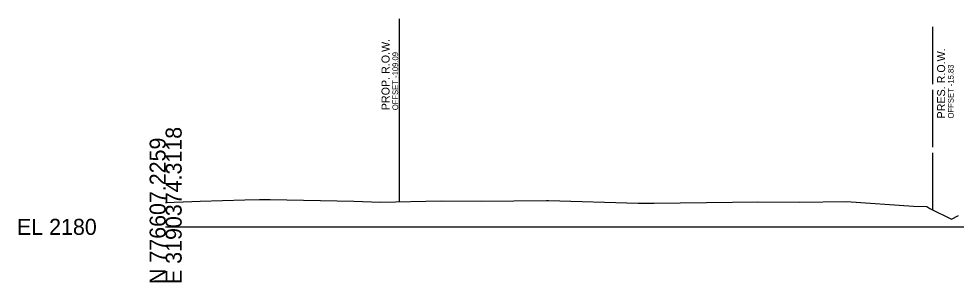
# Model space of a CAD drawing. Extents: x -26 to 303, y -10 to 13517.
# Drawn here: x -25.7 to 138.3, y 9490.3 to 9536.4 of the extents above; entities that cross this region are included whole.
import ezdxf

# ---------------------------------------------------------------- set-up
doc = ezdxf.new("R2010")
doc.units = 0
for name, color, linetype in [('DESIGN - ROW - Right-of-Way and Easement Labels', 7, 'Continuous'), ('DESIGN - ROW - Right-of-Way Linework', 7, 'Continuous'), ('DESIGN - SHEET - Light Grid', 7, 'Continuous'), ('SURVEY - GROUND - Top of Ground', 7, 'Continuous'), ('SURVEY - PROPERTY - ROW Lines', 7, 'Continuous'), ('SURVEY - PROPERTY - ROW Lines Text', 7, 'Continuous')]:
    doc.layers.add(name, color=color, linetype=linetype)

msp = doc.modelspace()

# ---------------------------------------------------------------- linework, layer by layer
at = {"layer": 'DESIGN - ROW - Right-of-Way Linework'}
msp.add_line((40.91, 9504.4), (40.91, 9536.4), dxfattribs=at)
at = {"layer": 'DESIGN - SHEET - Light Grid'}
msp.add_line((0, 9500), (150, 9500), dxfattribs=at)
at = {"layer": 'SURVEY - GROUND - Top of Ground'}
msp.add_lwpolyline([(0, 9504.28), (4.59, 9504.45), (6.06, 9504.5), (13.83, 9504.74), (16.42, 9504.79), (18.25, 9504.76), (32.92, 9504.47), (37.5, 9504.34), (48.19, 9504.53), (55.16, 9504.52), (66.59, 9504.6), (66.98, 9504.6), (82.61, 9504.15), (85.44, 9504.16), (99.14, 9504.34), (103.56, 9504.39), (110.84, 9504.32), (119.09, 9504.43), (130.79, 9503.62), (133.1, 9503.54), (133.64, 9503.22), (137.43, 9501.35), (138.65, 9501.96)], dxfattribs=at)
at = {"layer": 'SURVEY - PROPERTY - ROW Lines'}
for p, q in [((134.17, 9524.96), (134.17, 9534.96)), ((134.17, 9513.96), (134.17, 9523.96)), ((134.17, 9502.96), (134.17, 9512.96))]:
    msp.add_line(p, q, dxfattribs=at)

# ---------------------------------------------------------------- texts
at = {"layer": 'DESIGN - ROW - Right-of-Way and Easement Labels'}
for s, height, p in [('PROP. R.O.W.', 1.4, (39.16, 9520.4)), ('OFFSET -109.09', 1, (40.66, 9520.4))]:
    msp.add_text(s, height=height, rotation=90, dxfattribs=at).set_placement(p)
at = {"layer": 'DESIGN - SHEET - Light Grid'}
for s, p in [('E 3190374.3118', (2.8, 9490)), ('N 776607.2259', (0, 9490))]:
    msp.add_text(s, height=2.8, rotation=90, dxfattribs=at).set_placement(p)
msp.add_text('EL 2180', height=2.8, dxfattribs=at).set_placement((-26, 9498.6))
at = {"layer": 'SURVEY - PROPERTY - ROW Lines Text'}
for s, height, p in [('PRES. R.O.W.', 1.4, (136.32, 9518.96)), ('OFFSET -15.83', 1, (137.82, 9518.96))]:
    msp.add_text(s, height=height, rotation=90, dxfattribs=at).set_placement(p)

doc.saveas('drawing.dxf')
